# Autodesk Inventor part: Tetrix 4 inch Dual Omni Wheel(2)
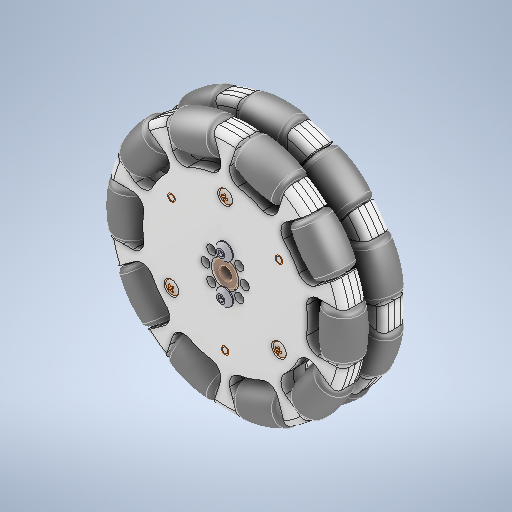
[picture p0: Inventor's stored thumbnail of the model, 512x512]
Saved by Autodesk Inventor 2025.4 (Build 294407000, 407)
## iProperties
Created: 2021-10
Part Number: Tetrix 4 inch Dual Omni Wheel(2)
Material: Genérico
Document SubType Name: Modeling
Designer: usuario
Density: 1 g/cm^3
Appearance: Valor por defecto
Author: usuario
Sending System: SolidWorks 2016
Last Author: LENOVO
Last Saved: 2021-10-21
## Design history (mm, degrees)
feature "36466_TXM-4 inch Omni Wheel-1-solid3"
feature "36466_TXM-4 inch Omni Wheel-1-solid9"
feature "36466_TXM-4 inch Omni Wheel-2-solid11"
feature "36466_TXM-4 inch Omni Wheel-2-solid3"
feature "36466_TXM-4 inch Omni Wheel-2-solid5"
feature "36466_TXM-4 inch Omni Wheel-2-solid30"
feature "36466_TXM-4 inch Omni Wheel-1-solid10"
feature "36466_TXM-4 inch Omni Wheel-2-solid38"
feature "36466_TXM-Omni Wheel Joining Hub-1-solid1"
feature "36466_TXM-4 inch Omni Wheel-2-solid18"
feature "36466_TXM-4 inch Omni Wheel-2-solid7"
feature "36466_TXM-4 inch Omni Wheel-2-solid9"
feature "36466_TXM-4 inch Omni Wheel-2-solid19"
feature "36466_TXM-4 inch Omni Wheel-1-solid31"
feature "36466_TXM-4 inch Omni Wheel-1-solid19"
feature "36466_TXM-4 inch Omni Wheel-2-solid2"
feature "36466_TXM-4 inch Omni Wheel-2-solid31"
feature "36466_TXM-4 inch Omni Wheel-1-solid25"
feature "39111_TXM-BHCS 6-32 x 0.375-3-solid1"
feature "36466_TXM-4 inch Omni Wheel-1-solid18"
feature "39111_TXM-BHCS 6-32 x 0.375-1-solid1"
feature "36466_TXM-4 inch Omni Wheel-1-solid35"
feature "36466_TXM-4 inch Omni Wheel-2-solid15"
feature "36466_TXM-4 inch Omni Wheel-2-solid25"
feature "36466_TXM-4 inch Omni Wheel-2-solid20"
feature "36466_TXM-4 inch Omni Wheel-1-solid13"
feature "36466_TXM-4 inch Omni Wheel-1-solid29"
feature "39111_TXM-BHCS 6-32 x 0.375-4-solid1"
feature "36466_TXM-4 inch Omni Wheel-2-solid16"
feature "36466_TXM-4 inch Omni Wheel-1-solid15"
feature "36466_TXM-4 inch Omni Wheel-2-solid24"
feature "36466_TXM-4 inch Omni Wheel-2-solid17"
feature "36466_TXM-4 inch Omni Wheel-2-solid34"
feature "36466_TXM-4 inch Omni Wheel-2-solid1"
feature "36466_TXM-4 inch Omni Wheel-2-solid23"
feature "36466_TXM-4 inch Omni Wheel-1-solid4"
feature "36466_TXM-4 inch Omni Wheel-2-solid12"
feature "36466_TXM-4 inch Omni Wheel-1-solid14"
feature "36466_TXM-4 inch Omni Wheel-1-solid32"
feature "36466_TXM-4 inch Omni Wheel-1-solid8"
feature "36466_TXM-4 inch Omni Wheel-2-solid28"
feature "36466_TXM-4 inch Omni Wheel-2-solid37"
feature "36466_TXM-4 inch Omni Wheel-2-solid6"
feature "36466_TXM-4 inch Omni Wheel-1-solid12"
feature "36466_TXM-4 inch Omni Wheel-1-solid24"
feature "36466_TXM-4 inch Omni Wheel-1-solid20"
feature "39111_TXM-BHCS 6-32 x 0.375-2-solid1"
feature "36466_TXM-4 inch Omni Wheel-1-solid7"
feature "36466_TXM-4 inch Omni Wheel-2-solid27"
feature "39091_TXM-Bronze Bushing-2-solid1"
feature "36466_TXM-4 inch Omni Wheel-1-solid34"
feature "36466_TXM-4 inch Omni Wheel-2-solid8"
feature "36466_TXM-4 inch Omni Wheel-1-solid16"
feature "36466_TXM-4 inch Omni Wheel-2-solid29"
feature "36466_TXM-4 inch Omni Wheel-1-solid5"
feature "36466_TXM-4 inch Omni Wheel-2-solid21"
feature "36466_TXM-4 inch Omni Wheel-1-solid27"
feature "36466_TXM-4 inch Omni Wheel-1-solid36"
feature "36466_TXM-4 inch Omni Wheel-2-solid22"
feature "36466_TXM-4 inch Omni Wheel-2-solid10"
feature "36466_TXM-4 inch Omni Wheel-1-solid30"
feature "36466_TXM-4 inch Omni Wheel-1-solid26"
feature "36466_TXM-4 inch Omni Wheel-2-solid13"
feature "36466_TXM-4 inch Omni Wheel-1-solid6"
feature "36466_TXM-4 inch Omni Wheel-2-solid14"
feature "36466_TXM-4 inch Omni Wheel-1-solid38"
feature "36466_TXM-4 inch Omni Wheel-1-solid22"
feature "36466_TXM-4 inch Omni Wheel-1-solid2"
feature "36466_TXM-4 inch Omni Wheel-2-solid4"
feature "39091_TXM-Bronze Bushing-1-solid1"
feature "36466_TXM-4 inch Omni Wheel-2-solid36"
feature "36466_TXM-4 inch Omni Wheel-1-solid11"
feature "36466_TXM-4 inch Omni Wheel-2-solid32"
feature "36466_TXM-4 inch Omni Wheel-1-solid37"
feature "36466_TXM-4 inch Omni Wheel-1-solid21"
feature "36466_TXM-4 inch Omni Wheel-2-solid26"
feature "36466_TXM-4 inch Omni Wheel-1-solid1"
feature "36466_TXM-4 inch Omni Wheel-1-solid28"
feature "36466_TXM-4 inch Omni Wheel-1-solid17"
feature "36466_TXM-4 inch Omni Wheel-1-solid33"
feature "36466_TXM-4 inch Omni Wheel-2-solid33"
feature "36466_TXM-4 inch Omni Wheel-1-solid23"
feature "36466_TXM-4 inch Omni Wheel-2-solid35"
node "Sólido1"
node "Sólido2"
node "Sólido3"
node "Sólido4"
node "Sólido5"
node "Sólido6"
node "Sólido7"
node "Sólido8"
node "Sólido9"
node "Sólido10"
node "Sólido11"
node "Sólido12"
node "Sólido13"
node "Sólido14"
node "Sólido15"
node "Sólido16"
node "Sólido17"
node "Sólido18"
node "Sólido19"
node "Sólido20"
node "Sólido21"
node "Sólido22"
node "Sólido23"
node "Sólido24"
node "Sólido25"
node "Sólido26"
node "Sólido27"
node "Sólido28"
node "Sólido29"
node "Sólido30"
node "Sólido31"
node "Sólido32"
node "Sólido33"
node "Sólido34"
node "Sólido35"
node "Sólido36"
node "Sólido37"
node "Sólido38"
node "Sólido39"
node "Sólido40"
node "Sólido41"
node "Sólido42"
node "Sólido43"
node "Sólido44"
node "Sólido45"
node "Sólido46"
node "Sólido47"
node "Sólido48"
node "Sólido49"
node "Sólido50"
node "Sólido51"
node "Sólido52"
node "Sólido53"
node "Sólido54"
node "Sólido55"
node "Sólido56"
node "Sólido57"
node "Sólido58"
node "Sólido59"
node "Sólido60"
node "Sólido61"
node "Sólido62"
node "Sólido63"
node "Sólido64"
node "Sólido65"
node "Sólido66"
node "Sólido67"
node "Sólido68"
node "Sólido69"
node "Sólido70"
node "Sólido71"
node "Sólido72"
node "Sólido73"
node "Sólido74"
node "Sólido75"
node "Sólido76"
node "Sólido77"
node "Sólido78"
node "Sólido79"
node "Sólido80"
node "Sólido81"
node "Sólido82"
node "Sólido83"
